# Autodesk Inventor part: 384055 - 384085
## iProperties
Created: 2006-01
Part Number: 384055 - 384085
Material: Standard
Document SubType Name: Modeling
Designer: I.Baliuc
Manufacturer: Standard
Standards Organization: Custom
Description: Elektra - Gießharz
Density: 1 g/cm^3
Author: I.Baliuc
Revision Number: 384055 - 384085
Comments: 384085: Härter PU88 - 37,5 gr 384055: Gießharz PU123 Beige - 131,2 gr
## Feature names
1. Basis1
2. Extrusion1
3. Extrusion2
